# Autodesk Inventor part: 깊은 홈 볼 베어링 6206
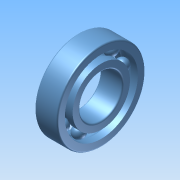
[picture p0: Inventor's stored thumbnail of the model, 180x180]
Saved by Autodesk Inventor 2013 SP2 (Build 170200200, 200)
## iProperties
Created: 2025-06
Part Number: 깊은 홈 볼 베어링 6206
Material: Generic
Document SubType Name: Modeling
Designer: a
Density: 1 g/cm^3
Author: a
변환 표준: STEP AP214IS
전처리기: Build: 200, Release: 2013 SP2 Update 6 - Date: Thu 07/17/2014
전송 단위: 밀리미터
불확실성: 0.01
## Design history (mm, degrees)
node "깊은 홈 볼 베어링 62061"
body "Solid1"
node "Solid1_1"
node "Solid1_2"
node "Solid1_3"
node "Solid1_4"
node "Solid1_5"
node "Solid1_6"
node "Solid1_7"
node "Solid1_8"
node "Solid1_9"
node "Solid1_10"
node "기준1"
node "기준2"
node "기준3"
node "기준4"
node "기준5"
node "기준6"
node "기준7"
node "기준8"
node "기준9"
node "기준10"
node "기준11"
